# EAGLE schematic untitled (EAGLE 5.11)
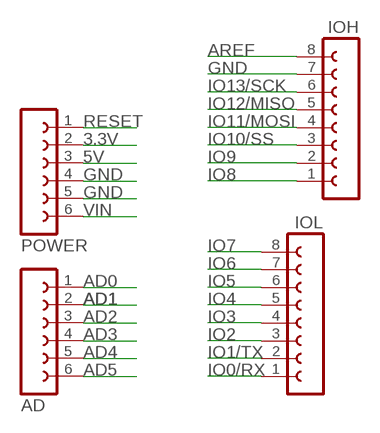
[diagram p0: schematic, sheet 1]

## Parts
AD  FE06-1  [FE06]
IOH  FE08-1  [FE08]
IOL  FE08-1  [FE08]
POWER  FE06-1  [FE06]

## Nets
3.3V: POWER.2
5V: POWER.3
AD0: AD.1
AD1: AD.2
AD2: AD.3
AD3: AD.4
AD4: AD.5
AD5: AD.6
AREF: IOH.8
GND: IOH.7 POWER.4 POWER.5
IO0/RX: IOL.1
IO1/TX: IOL.2
IO2: IOL.3
IO3: IOL.4
IO4: IOL.5
IO5: IOL.6
IO6: IOL.7
IO7: IOL.8
IO8: IOH.1
IO9: IOH.2
IO10/SS: IOH.3
IO11/MOSI: IOH.4
IO12/MISO: IOH.5
IO13/SCK: IOH.6
RESET: POWER.1
VIN: POWER.6

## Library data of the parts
AD POWER = con-lsta:FE06-1: FEMALE HEADER; OC_FARNELL: unknown; OC_NEWARK: unknown
IOH IOL = con-lsta:FE08-1: FEMALE HEADER; OC_FARNELL: unknown; OC_NEWARK: unknown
